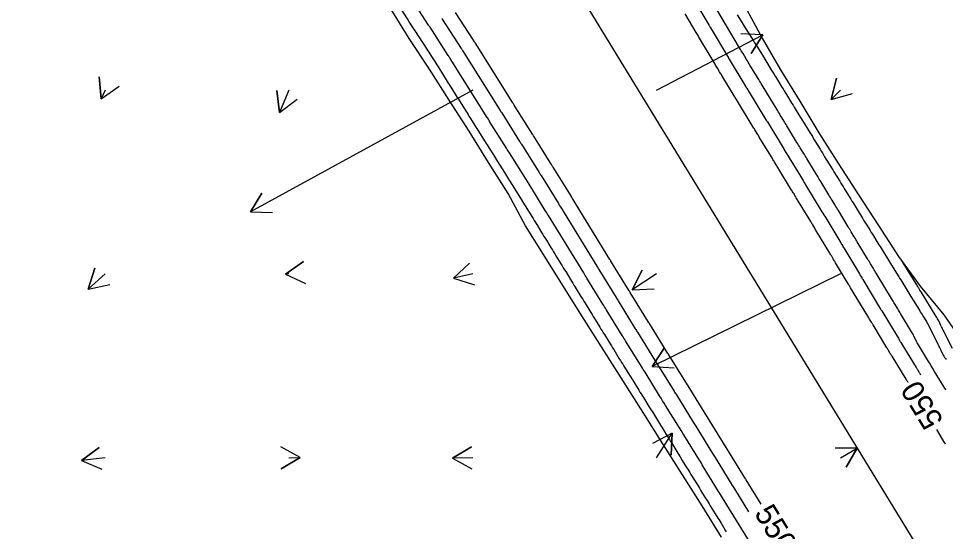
# Model space of a CAD drawing. Extents: x 954385 to 988206, y 1868364 to 1924553.
# Drawn here: x 956633.6 to 956885.7, y 1921348.9 to 1921488.4 of the extents above; entities that cross this region are included whole.
import ezdxf

# ---------------------------------------------------------------- set-up
doc = ezdxf.new("R2010")
doc.units = 0
for name, color, linetype in [('Default', 7, 'Continuous'), ('Ex_Contour Labels', 7, 'Continuous'), ('Ex_Major Contours', 7, 'Continuous'), ('Ex_Minor Contours', 7, 'Continuous'), ('Perimeter', 7, 'Continuous'), ('Slopes', 7, 'Continuous')]:
    doc.layers.add(name, color=color, linetype=linetype)

msp = doc.modelspace()

# ---------------------------------------------------------------- linework, layer by layer
at = {"layer": 'Default'}
msp.add_line((957221.14, 1920784.24), (956045.8, 1922705.18), dxfattribs=at)
at = {"layer": 'Ex_Major Contours'}
for points in [[(956835.53, 1921356.32), (956831.44, 1921362.96), (956831.36, 1921363.1), (956831.27, 1921363.23), (956826.2, 1921371.47), (956826.15, 1921371.54), (956826.11, 1921371.61), (956826.07, 1921371.68), (956826.02, 1921371.75), (956820.95, 1921379.96), (956820.9, 1921380.03), (956820.85, 1921380.11), (956820.8, 1921380.19), (956820.75, 1921380.27), (956815.69, 1921388.44), (956815.64, 1921388.53), (956815.59, 1921388.62), (956815.53, 1921388.71), (956815.48, 1921388.79), (956810.43, 1921396.91), (956810.37, 1921397.01), (956810.31, 1921397.11), (956810.25, 1921397.21), (956810.19, 1921397.31), (956805.18, 1921405.4), (956805.11, 1921405.5), (956805.04, 1921405.61), (956804.98, 1921405.72), (956804.91, 1921405.83), (956799.94, 1921413.89), (956799.87, 1921414.01), (956799.8, 1921414.13), (956799.72, 1921414.24), (956799.65, 1921414.36), (956794.7, 1921422.4), (956794.63, 1921422.52), (956794.56, 1921422.64), (956794.48, 1921422.76), (956794.41, 1921422.88), (956784.24, 1921439.43), (956784.16, 1921439.55), (956784.08, 1921439.68), (956784, 1921439.81), (956783.93, 1921439.94), (956778.99, 1921447.92), (956778.91, 1921448.05), (956778.83, 1921448.19), (956778.74, 1921448.32), (956778.66, 1921448.46), (956773.7, 1921456.35), (956773.6, 1921456.51), (956773.51, 1921456.66), (956773.41, 1921456.81), (956773.32, 1921456.96), (956768.41, 1921464.79), (956768.3, 1921464.96), (956768.19, 1921465.13), (956768.09, 1921465.3), (956767.98, 1921465.48), (956757.82, 1921481.64), (956757.69, 1921481.86), (956757.56, 1921482.07), (956757.42, 1921482.28), (956757.28, 1921482.49), (956752.45, 1921489.97)], [(956875.51, 1921389.39), (956875.41, 1921389.55), (956875.3, 1921389.73), (956875.19, 1921389.91), (956875.07, 1921390.1), (956874.96, 1921390.28), (956871.15, 1921396.56), (956871.04, 1921396.75), (956870.92, 1921396.94), (956870.8, 1921397.13), (956870.69, 1921397.32), (956870.23, 1921398.08), (956870.11, 1921398.27), (956869.99, 1921398.46), (956869.88, 1921398.65), (956869.76, 1921398.84), (956866.02, 1921405.03), (956865.9, 1921405.23), (956865.78, 1921405.43), (956865.66, 1921405.62), (956865.54, 1921405.82), (956865.06, 1921406.62), (956864.94, 1921406.82), (956864.82, 1921407.02), (956864.7, 1921407.21), (956864.57, 1921407.41), (956859.89, 1921415.16), (956859.77, 1921415.36), (956859.64, 1921415.57), (956859.52, 1921415.78), (956859.39, 1921415.99), (956855.8, 1921421.94), (956855.67, 1921422.16), (956855.54, 1921422.38), (956855.4, 1921422.6), (956855.27, 1921422.82), (956854.74, 1921423.7), (956854.61, 1921423.92), (956854.48, 1921424.14), (956854.34, 1921424.36), (956854.21, 1921424.58), (956850.7, 1921430.4), (956850.56, 1921430.63), (956850.42, 1921430.86), (956850.28, 1921431.09), (956850.14, 1921431.32), (956849.58, 1921432.24), (956849.44, 1921432.47), (956849.3, 1921432.7), (956849.17, 1921432.93), (956849.03, 1921433.15), (956845.55, 1921438.88), (956845.41, 1921439.11), (956845.27, 1921439.35), (956845.12, 1921439.59), (956844.98, 1921439.82), (956844.4, 1921440.77), (956844.26, 1921441.01), (956844.12, 1921441.24), (956843.97, 1921441.48), (956843.83, 1921441.72), (956840.39, 1921447.37), (956840.24, 1921447.61), (956840.1, 1921447.85), (956839.95, 1921448.09), (956839.8, 1921448.34), (956839.21, 1921449.3), (956839.07, 1921449.55), (956838.92, 1921449.79), (956838.77, 1921450.03), (956838.62, 1921450.27), (956835.21, 1921455.87), (956835.06, 1921456.12), (956834.91, 1921456.36), (956834.76, 1921456.61), (956834.61, 1921456.86), (956834.02, 1921457.84), (956833.87, 1921458.08), (956833.72, 1921458.33), (956833.57, 1921458.57), (956833.42, 1921458.82), (956828.82, 1921466.37), (956828.67, 1921466.62), (956828.52, 1921466.87), (956828.36, 1921467.12), (956828.21, 1921467.37), (956824.89, 1921472.86), (956824.73, 1921473.11), (956824.58, 1921473.37), (956824.42, 1921473.63), (956824.26, 1921473.88), (956823.64, 1921474.91), (956823.49, 1921475.16), (956823.33, 1921475.42), (956823.18, 1921475.68), (956823.02, 1921475.94), (956818.54, 1921483.46), (956818.38, 1921483.74), (956818.21, 1921484.01), (956818.05, 1921484.29), (956817.88, 1921484.56), (956814.85, 1921489.64)], [(956885.69, 1921372.64), (956885.61, 1921372.78), (956885.58, 1921372.83), (956885.55, 1921372.87), (956883.3, 1921376.57)]]:
    msp.add_lwpolyline(points, dxfattribs=at)
at = {"layer": 'Ex_Minor Contours'}
for points in [[(956811.4, 1921503.25), (956821.3, 1921486.65), (956821.36, 1921486.54), (956821.43, 1921486.43), (956821.59, 1921486.15), (956821.66, 1921486.04), (956821.69, 1921485.99), (956826.65, 1921477.66), (956826.7, 1921477.58), (956826.74, 1921477.51), (956826.79, 1921477.43), (956826.83, 1921477.36), (956831.42, 1921469.79), (956831.52, 1921469.63), (956831.62, 1921469.46), (956831.83, 1921469.12), (956831.88, 1921469.04), (956831.93, 1921468.96), (956831.98, 1921468.87), (956832.03, 1921468.79), (956837.02, 1921460.59), (956837.08, 1921460.5), (956837.13, 1921460.42), (956837.18, 1921460.33), (956837.24, 1921460.24), (956841.77, 1921452.79), (956841.82, 1921452.7), (956841.88, 1921452.61), (956841.94, 1921452.52), (956841.99, 1921452.43), (956842.27, 1921451.97), (956842.44, 1921451.69), (956846.95, 1921444.29), (956847.01, 1921444.19), (956847.07, 1921444.1), (956847.12, 1921444), (956847.18, 1921443.91), (956847.41, 1921443.52), (956847.47, 1921443.43), (956847.53, 1921443.33), (956847.59, 1921443.24), (956847.65, 1921443.14), (956852.09, 1921435.81), (956852.15, 1921435.71), (956852.22, 1921435.6), (956852.28, 1921435.5), (956852.34, 1921435.4), (956852.59, 1921434.99), (956852.65, 1921434.89), (956852.72, 1921434.78), (956852.78, 1921434.68), (956852.84, 1921434.58), (956857.21, 1921427.35), (956857.28, 1921427.23), (956857.35, 1921427.12), (956857.42, 1921427.01), (956857.48, 1921426.9), (956857.75, 1921426.45), (956857.82, 1921426.34), (956857.89, 1921426.23), (956857.96, 1921426.11), (956858.03, 1921426), (956862.3, 1921418.9), (956862.38, 1921418.78), (956862.45, 1921418.65), (956862.53, 1921418.53), (956862.6, 1921418.41), (956862.9, 1921417.91), (956862.98, 1921417.78), (956863.05, 1921417.66), (956863.13, 1921417.54), (956863.2, 1921417.41), (956868.06, 1921409.37), (956868.15, 1921409.24), (956868.23, 1921409.1), (956868.31, 1921408.97), (956868.39, 1921408.84), (956872.54, 1921401.97), (956872.71, 1921401.69), (956872.89, 1921401.4), (956873.23, 1921400.83), (956873.32, 1921400.69), (956873.4, 1921400.55), (956873.49, 1921400.41), (956873.58, 1921400.26), (956877.7, 1921393.48), (956877.79, 1921393.34), (956877.88, 1921393.19), (956877.97, 1921393.04), (956878.06, 1921392.89), (956878.42, 1921392.3), (956878.51, 1921392.15), (956878.6, 1921392), (956878.69, 1921391.85), (956878.78, 1921391.71), (956878.93, 1921391.47)], [(956835, 1921341.92), (956825.07, 1921358.05), (956824.8, 1921358.48), (956824.53, 1921358.92), (956824.26, 1921359.36), (956823.99, 1921359.79), (956819.81, 1921366.58), (956819.55, 1921367.01), (956819.29, 1921367.43), (956819.02, 1921367.86), (956818.76, 1921368.29), (956814.53, 1921375.13), (956814.28, 1921375.53), (956814.03, 1921375.94), (956813.77, 1921376.35), (956813.52, 1921376.75), (956809.57, 1921383.13), (956809.17, 1921383.79), (956808.76, 1921384.44), (956808.35, 1921385.1), (956807.95, 1921385.75), (956803.97, 1921392.17), (956803.73, 1921392.55), (956803.49, 1921392.94), (956803.25, 1921393.33), (956803.01, 1921393.71), (956798.68, 1921400.7), (956798.45, 1921401.07), (956798.22, 1921401.44), (956797.99, 1921401.81), (956797.76, 1921402.18), (956793.41, 1921409.23), (956793.19, 1921409.59), (956792.97, 1921409.95), (956792.75, 1921410.31), (956792.53, 1921410.67), (956788.17, 1921417.76), (956787.95, 1921418.12), (956787.73, 1921418.47), (956787.51, 1921418.82), (956787.3, 1921419.17), (956777.67, 1921434.83), (956777.47, 1921435.17), (956777.26, 1921435.51), (956777.05, 1921435.84), (956776.84, 1921436.18), (956772.9, 1921442.56), (956772.45, 1921443.29), (956772, 1921444.01), (956771.55, 1921444.74), (956771.09, 1921445.46), (956767.07, 1921451.88), (956766.87, 1921452.18), (956766.68, 1921452.48), (956766.49, 1921452.79), (956766.3, 1921453.09), (956761.71, 1921460.41), (956761.54, 1921460.68), (956761.37, 1921460.96), (956761.2, 1921461.23), (956761.03, 1921461.5), (956751, 1921477.47), (956750.87, 1921477.68), (956750.73, 1921477.89), (956750.6, 1921478.1), (956750.46, 1921478.31), (956745.49, 1921486), (956745.4, 1921486.15), (956745.3, 1921486.29), (956745.21, 1921486.44), (956745.11, 1921486.59), (956739.97, 1921494.54)], [(956737.28, 1921491.33), (956739.23, 1921488.31), (956739.5, 1921487.9), (956739.77, 1921487.49), (956740.03, 1921487.08), (956740.3, 1921486.67), (956741.36, 1921485.03), (956741.63, 1921484.62), (956741.89, 1921484.21), (956742.16, 1921483.8), (956742.42, 1921483.39), (956744.58, 1921480.05), (956744.85, 1921479.62), (956745.13, 1921479.2), (956745.4, 1921478.78), (956745.68, 1921478.35), (956746.77, 1921476.66), (956747.05, 1921476.23), (956747.32, 1921475.81), (956747.59, 1921475.38), (956747.86, 1921474.95), (956749.89, 1921471.71), (956750.17, 1921471.27), (956750.44, 1921470.83), (956750.72, 1921470.4), (956750.99, 1921469.96), (956752.09, 1921468.21), (956752.36, 1921467.77), (956752.64, 1921467.34), (956752.91, 1921466.9), (956753.19, 1921466.46), (956755.29, 1921463.12), (956755.55, 1921462.69), (956755.82, 1921462.27), (956756.09, 1921461.84), (956756.36, 1921461.42), (956757.42, 1921459.72), (956757.69, 1921459.29), (956757.96, 1921458.87), (956758.22, 1921458.44), (956758.49, 1921458.02), (956760.47, 1921454.87), (956760.75, 1921454.42), (956761.03, 1921453.98), (956761.31, 1921453.53), (956761.59, 1921453.08), (956762.71, 1921451.29), (956762.99, 1921450.84), (956763.27, 1921450.4), (956763.55, 1921449.95), (956763.83, 1921449.5), (956765.73, 1921446.49), (956766.01, 1921446.03), (956766.3, 1921445.58), (956766.58, 1921445.12), (956766.87, 1921444.66), (956768.02, 1921442.84), (956768.3, 1921442.38), (956768.59, 1921441.93), (956768.87, 1921441.47), (956769.16, 1921441.01), (956770.34, 1921439.09), (956770.64, 1921438.61), (956770.93, 1921438.14), (956771.22, 1921437.67), (956771.51, 1921437.19), (956773.18, 1921434.49), (956773.52, 1921433.95), (956773.85, 1921433.42), (956774.18, 1921432.88), (956774.51, 1921432.35), (956775.84, 1921430.18), (956776.16, 1921429.65), (956776.49, 1921429.12), (956776.81, 1921428.6), (956777.13, 1921428.07), (956778.43, 1921425.96), (956778.76, 1921425.43), (956779.08, 1921424.9), (956779.41, 1921424.37), (956779.73, 1921423.84), (956781.1, 1921421.63), (956781.42, 1921421.1), (956781.74, 1921420.58), (956782.06, 1921420.05), (956782.39, 1921419.53), (956783.68, 1921417.43), (956784, 1921416.91), (956784.32, 1921416.38), (956784.64, 1921415.86), (956784.97, 1921415.33), (956786.37, 1921413.04), (956786.69, 1921412.53), (956787.01, 1921412.01), (956787.33, 1921411.49), (956787.65, 1921410.97), (956788.92, 1921408.9), (956789.24, 1921408.38), (956789.56, 1921407.86), (956789.88, 1921407.34), (956790.2, 1921406.83), (956791.67, 1921404.44), (956791.98, 1921403.93), (956792.3, 1921403.42), (956792.61, 1921402.92), (956792.93, 1921402.41), (956794.18, 1921400.37), (956794.5, 1921399.86), (956794.81, 1921399.35), (956795.12, 1921398.84), (956795.44, 1921398.34), (956796.98, 1921395.86), (956797.29, 1921395.36), (956797.6, 1921394.86), (956797.91, 1921394.35), (956798.22, 1921393.85), (956799.46, 1921391.85), (956799.77, 1921391.35), (956800.08, 1921390.85), (956800.39, 1921390.35), (956800.7, 1921389.85), (956802.29, 1921387.29), (956802.59, 1921386.8), (956802.9, 1921386.3), (956803.21, 1921385.81), (956803.51, 1921385.31), (956804.74, 1921383.34), (956805.04, 1921382.85), (956805.35, 1921382.35), (956805.66, 1921381.86), (956805.96, 1921381.37), (956807.6, 1921378.72), (956807.9, 1921378.24), (956808.2, 1921377.75), (956808.5, 1921377.26), (956808.8, 1921376.78), (956810.01, 1921374.83), (956810.31, 1921374.34), (956810.61, 1921373.85), (956810.91, 1921373.36), (956811.22, 1921372.88), (956812.91, 1921370.14), (956813.5, 1921369.18), (956814.09, 1921368.22), (956815.28, 1921366.31), (956815.58, 1921365.83), (956815.87, 1921365.35), (956816.17, 1921364.87), (956816.47, 1921364.39), (956818.21, 1921361.55), (956818.5, 1921361.08), (956818.79, 1921360.61), (956819.08, 1921360.14), (956819.37, 1921359.66), (956820.54, 1921357.78), (956820.83, 1921357.3), (956821.12, 1921356.83), (956821.41, 1921356.36), (956821.7, 1921355.89), (956823.52, 1921352.93), (956823.81, 1921352.47), (956824.09, 1921352.01), (956824.37, 1921351.55), (956824.66, 1921351.09), (956825.79, 1921349.24), (956826.08, 1921348.78)], [(956885.82, 1921387.34), (956885.66, 1921387.61), (956885.49, 1921387.89), (956885.32, 1921388.16), (956882.75, 1921392.4), (956882.27, 1921393.18), (956881.79, 1921393.96), (956881.32, 1921394.74), (956880.84, 1921395.52), (956878.34, 1921399.63), (956878.17, 1921399.92), (956878.01, 1921400.21), (956877.85, 1921400.51), (956877.7, 1921400.81), (956877.11, 1921402.03), (956876.96, 1921402.33), (956876.8, 1921402.63), (956876.64, 1921402.92), (956876.47, 1921403.21), (956873.46, 1921408.18), (956873.28, 1921408.48), (956873.1, 1921408.78), (956872.92, 1921409.08), (956872.73, 1921409.38), (956872, 1921410.59), (956871.82, 1921410.89), (956871.64, 1921411.19), (956871.46, 1921411.49), (956871.27, 1921411.79), (956866.86, 1921419.1), (956866.66, 1921419.42), (956866.46, 1921419.75), (956866.27, 1921420.07), (956866.07, 1921420.4), (956865.29, 1921421.7), (956865.09, 1921422.03), (956864.89, 1921422.35), (956864.7, 1921422.68), (956864.5, 1921423.01), (956861.71, 1921427.63), (956861.51, 1921427.97), (956861.3, 1921428.31), (956861.09, 1921428.65), (956860.89, 1921429), (956860.06, 1921430.37), (956859.85, 1921430.71), (956859.64, 1921431.05), (956859.44, 1921431.39), (956859.23, 1921431.74), (956856.56, 1921436.16), (956856.34, 1921436.51), (956856.13, 1921436.87), (956855.91, 1921437.23), (956855.7, 1921437.58), (956854.83, 1921439.01), (956854.61, 1921439.37), (956854.4, 1921439.72), (956854.18, 1921440.08), (956853.97, 1921440.44), (956851.79, 1921444.02), (956851.37, 1921444.72), (956850.94, 1921445.42), (956850.52, 1921446.12), (956850.09, 1921446.82), (956847.98, 1921450.29), (956847.76, 1921450.66), (956847.53, 1921451.02), (956847.31, 1921451.39), (956847.08, 1921451.76), (956846.19, 1921453.23), (956845.97, 1921453.59), (956845.74, 1921453.96), (956845.52, 1921454.33), (956845.29, 1921454.7), (956842.81, 1921458.77), (956842.58, 1921459.15), (956842.36, 1921459.52), (956842.13, 1921459.89), (956841.9, 1921460.27), (956840.99, 1921461.76), (956840.77, 1921462.13), (956840.54, 1921462.5), (956840.31, 1921462.88), (956840.09, 1921463.25), (956835.8, 1921470.29), (956835.57, 1921470.66), (956835.34, 1921471.04), (956835.11, 1921471.42), (956834.88, 1921471.8), (956832.51, 1921475.7), (956832.28, 1921476.09), (956832.04, 1921476.48), (956831.81, 1921476.87), (956831.57, 1921477.26), (956830.63, 1921478.82), (956830.39, 1921479.21), (956830.16, 1921479.6), (956829.92, 1921479.99), (956829.69, 1921480.38), (956823.46, 1921490.83)], [(956748.71, 1921488.38), (956748.77, 1921488.29), (956748.83, 1921488.21), (956753.98, 1921480.24), (956754.06, 1921480.11), (956754.14, 1921479.98), (956754.23, 1921479.85), (956754.31, 1921479.72), (956764.56, 1921463.39), (956764.67, 1921463.22), (956764.78, 1921463.04), (956764.89, 1921462.87), (956765, 1921462.7), (956769.85, 1921454.96), (956769.97, 1921454.76), (956770.1, 1921454.57), (956770.22, 1921454.38), (956770.34, 1921454.18), (956775.15, 1921446.53), (956775.28, 1921446.32), (956775.41, 1921446.1), (956775.55, 1921445.89), (956775.68, 1921445.67), (956780.39, 1921438.04), (956780.53, 1921437.82), (956780.67, 1921437.59), (956780.81, 1921437.37), (956780.95, 1921437.15), (956790.86, 1921421.02), (956791, 1921420.79), (956791.14, 1921420.56), (956791.29, 1921420.32), (956791.43, 1921420.09), (956796.09, 1921412.51), (956796.24, 1921412.28), (956796.38, 1921412.04), (956796.53, 1921411.8), (956796.67, 1921411.56), (956801.33, 1921404.01), (956801.48, 1921403.77), (956801.63, 1921403.53), (956801.78, 1921403.28), (956801.93, 1921403.04), (956806.59, 1921395.53), (956806.74, 1921395.28), (956806.9, 1921395.03), (956807.06, 1921394.78), (956807.21, 1921394.52), (956811.85, 1921387.05), (956812.01, 1921386.79), (956812.17, 1921386.53), (956812.34, 1921386.27), (956812.5, 1921386.01), (956817.1, 1921378.57), (956817.27, 1921378.3), (956817.44, 1921378.03), (956817.61, 1921377.75), (956817.77, 1921377.48), (956822.35, 1921370.08), (956822.52, 1921369.8), (956822.7, 1921369.52), (956822.87, 1921369.24), (956823.04, 1921368.96), (956827.59, 1921361.58), (956827.77, 1921361.3), (956827.94, 1921361.01), (956828.12, 1921360.72), (956828.3, 1921360.43), (956832.12, 1921354.22)], [(956829.03, 1921489.4), (956830.14, 1921487.62), (956830.42, 1921487.18), (956830.69, 1921486.73), (956830.97, 1921486.29), (956831.25, 1921485.84), (956833.16, 1921482.78), (956833.46, 1921482.29), (956833.77, 1921481.8), (956834.07, 1921481.32), (956834.37, 1921480.83), (956835.88, 1921478.38), (956836.79, 1921476.9), (956838.31, 1921474.43), (956838.66, 1921473.86), (956839.01, 1921473.29), (956839.36, 1921472.72), (956839.71, 1921472.15), (956841.19, 1921469.74), (956841.5, 1921469.24), (956841.8, 1921468.74), (956842.11, 1921468.25), (956842.41, 1921467.75), (956843.63, 1921465.76), (956843.94, 1921465.27), (956844.24, 1921464.77), (956844.55, 1921464.27), (956844.85, 1921463.78), (956846.11, 1921461.73), (956846.42, 1921461.22), (956846.73, 1921460.72), (956847.04, 1921460.21), (956847.35, 1921459.7), (956848.8, 1921457.36), (956849.14, 1921456.8), (956849.48, 1921456.25), (956849.82, 1921455.69), (956850.16, 1921455.14), (956851.57, 1921452.84), (956851.89, 1921452.33), (956852.2, 1921451.82), (956852.51, 1921451.3), (956852.83, 1921450.79), (956854.08, 1921448.75), (956854.4, 1921448.24), (956854.71, 1921447.73), (956855.03, 1921447.22), (956855.34, 1921446.7), (956856.92, 1921444.14), (956857.22, 1921443.64), (956857.53, 1921443.15), (956857.83, 1921442.66), (956858.13, 1921442.17), (956859.35, 1921440.2), (956859.65, 1921439.7), (956859.95, 1921439.21), (956860.26, 1921438.72), (956860.56, 1921438.23), (956862.25, 1921435.5), (956862.54, 1921435.02), (956862.84, 1921434.54), (956863.13, 1921434.06), (956863.43, 1921433.58), (956864.62, 1921431.66), (956864.91, 1921431.18), (956865.21, 1921430.7), (956865.51, 1921430.22), (956865.8, 1921429.74), (956867.6, 1921426.83), (956867.89, 1921426.37), (956868.18, 1921425.91), (956868.46, 1921425.44), (956868.75, 1921424.98), (956869.9, 1921423.13), (956870.18, 1921422.66), (956870.47, 1921422.2), (956870.76, 1921421.73), (956871.04, 1921421.27), (956872.96, 1921418.17), (956873.23, 1921417.72), (956873.51, 1921417.28), (956873.79, 1921416.83), (956874.06, 1921416.38), (956875.17, 1921414.59), (956875.45, 1921414.14), (956875.72, 1921413.69), (956876, 1921413.24), (956876.28, 1921412.79), (956878.59, 1921409.04), (956878.83, 1921408.65), (956879.07, 1921408.27), (956879.31, 1921407.88), (956879.54, 1921407.49), (956880.5, 1921405.95), (956880.73, 1921405.56), (956880.95, 1921405.17), (956881.17, 1921404.77), (956881.37, 1921404.36), (956883.75, 1921399.56), (956883.92, 1921399.22), (956884.09, 1921398.88), (956884.26, 1921398.55), (956884.42, 1921398.21), (956885.09, 1921396.86), (956885.27, 1921396.53), (956885.47, 1921396.21), (956885.68, 1921395.9), (956885.92, 1921395.61)], [(956887.57, 1921398.59), (956885.07, 1921403.64), (956884.92, 1921403.95), (956884.76, 1921404.26), (956884.61, 1921404.57), (956884.45, 1921404.88), (956883.84, 1921406.12), (956883.68, 1921406.43), (956883.52, 1921406.74), (956883.35, 1921407.04), (956883.17, 1921407.33), (956879.04, 1921414.02), (956878.89, 1921414.27), (956878.74, 1921414.52), (956878.43, 1921415.01), (956878.36, 1921415.13), (956878.28, 1921415.26), (956878.21, 1921415.38), (956878.13, 1921415.5), (956874.16, 1921421.93)]]:
    msp.add_lwpolyline(points, dxfattribs=at)
at = {"layer": 'Perimeter'}
for points in [[(956824.81, 1921347.37), (956819.48, 1921355.83), (956814.15, 1921364.29), (956808.81, 1921372.75), (956803.45, 1921381.19), (956798.08, 1921389.63), (956792.73, 1921398.08), (956787.39, 1921406.53), (956782.08, 1921415.01), (956776.8, 1921423.5), (956771.5, 1921431.98), (956766.73, 1921440.79), (956761.4, 1921449.25), (956756.18, 1921457.78), (956750.7, 1921466.15), (956745.31, 1921474.58), (956739.85, 1921482.96), (956734.55, 1921491.44)], [(956831.07, 1921491.88), (956835.81, 1921483.05), (956840.83, 1921474.4), (956846.08, 1921465.89), (956851.23, 1921457.32), (956856.61, 1921448.89), (956861.99, 1921440.46), (956867.43, 1921432.06), (956872.87, 1921423.67), (956878.85, 1921415.6), (956885.2, 1921407.77), (956890.96, 1921399.57)]]:
    msp.add_lwpolyline(points, dxfattribs=at)
at = {"layer": 'Slopes'}
for points in [[(956807.13, 1921468.93), (956836.05, 1921483.93), (956832.82, 1921478.87), (956836.05, 1921483.93), (956830.06, 1921484.2)], [(956657.13, 1921468.93), (956656, 1921466.52), (956655.5, 1921472.5), (956656, 1921466.52), (956660.92, 1921469.95)], [(956857.13, 1921468.93), (956854.6, 1921466.31), (956856.05, 1921472.13), (956854.6, 1921466.31), (956860.36, 1921467.96)], [(956757.13, 1921468.93), (956696.62, 1921435.77), (956699.73, 1921440.9), (956696.62, 1921435.77), (956702.61, 1921435.64)], [(956707.13, 1921468.93), (956704.51, 1921462.81), (956703.8, 1921468.76), (956704.51, 1921462.81), (956709.31, 1921466.4)], [(956657.13, 1921418.93), (956652.49, 1921414.76), (956654.35, 1921420.46), (956652.49, 1921414.76), (956658.36, 1921416)], [(956707.13, 1921418.93), (956706.18, 1921418.85), (956711.12, 1921422.26), (956706.18, 1921418.85), (956711.59, 1921416.27)], [(956757.13, 1921418.93), (956751.85, 1921417.72), (956756.24, 1921421.8), (956751.85, 1921417.72), (956757.58, 1921415.95)], [(956807.13, 1921418.93), (956800.46, 1921414.56), (956803.16, 1921419.92), (956800.46, 1921414.56), (956806.45, 1921414.9)], [(956857.13, 1921418.93), (956805.87, 1921393.76), (956809.22, 1921398.74), (956805.87, 1921393.76), (956811.86, 1921393.36)], [(956807.13, 1921368.93), (956811.33, 1921375.6), (956811.1, 1921369.6), (956811.33, 1921375.6), (956806.02, 1921372.8)], [(956657.13, 1921368.93), (956650.7, 1921368.15), (956655.5, 1921371.75), (956650.7, 1921368.15), (956656.22, 1921365.8)], [(956707.13, 1921368.93), (956710.18, 1921368.98), (956705.04, 1921365.89), (956710.18, 1921368.98), (956704.94, 1921371.89)], [(956757.13, 1921368.93), (956751.58, 1921368.84), (956756.73, 1921371.92), (956751.58, 1921368.84), (956756.83, 1921365.92)], [(956857.13, 1921368.93), (956861.65, 1921371.57), (956858.68, 1921366.36), (956861.65, 1921371.57), (956855.65, 1921371.54)]]:
    msp.add_lwpolyline(points, dxfattribs=at)

# ---------------------------------------------------------------- texts
at = {"layer": 'Ex_Contour Labels'}
for rotation, p in [(121.2999, (956885.31, 1921379.05)), (301.5643, (956833.53, 1921353.83))]:
    msp.add_text('550', height=6, rotation=rotation, dxfattribs=at).set_placement(p)

doc.saveas('drawing.dxf')
